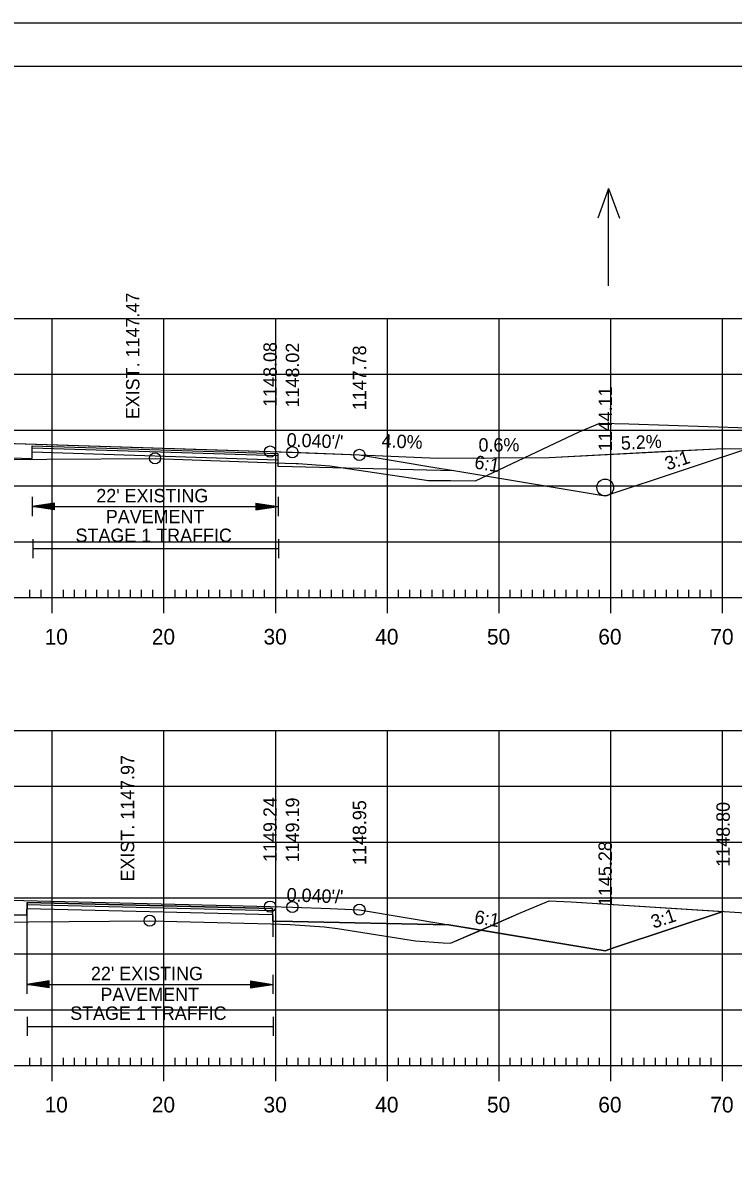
# Model space of a CAD drawing. Extents: x 1322838 to 1324533, y 339903 to 351025.
# Drawn here: x 1323711.1 to 1323774.7, y 342574.4 to 342676.5 of the extents above; entities that cross this region are included whole.
import ezdxf

# ---------------------------------------------------------------- set-up
doc = ezdxf.new("R2010")
doc.units = 0
for name, color, linetype in [('R_Alt Surface', 7, 'Continuous'), ('R_Axis', 7, 'Continuous'), ('R_Axis Annot', 7, 'Continuous'), ('R_Border', 7, 'Continuous'), ('R_Drive', 7, 'Continuous'), ('R_Exist Surface', 7, 'Continuous'), ('R_Fin Surface', 7, 'Continuous'), ('R_Fin Surface Annot', 7, 'Continuous'), ('R_Grid', 7, 'Continuous'), ('R_No Plot', 7, 'Continuous'), ('R_Water', 7, 'Continuous'), ('R_Water Annot', 7, 'Continuous'), ('R_Xsect Elev', 7, 'Continuous')]:
    doc.layers.add(name, color=color, linetype=linetype)

msp = doc.modelspace()

# ---------------------------------------------------------------- linework, layer by layer
at = {"layer": 'R_Alt Surface'}
for points in [[(1323655.31, 342638.41), (1323672.21, 342638.74), (1323711.91, 342637.5), (1323711.92, 342638.63), (1323733.91, 342637.94), (1323733.92, 342636.82), (1323735.22, 342636.78), (1323749.68, 342636.42)], [(1323655.61, 342597.23), (1323672.21, 342597.56), (1323711.45, 342596.62), (1323711.46, 342597.75), (1323733.44, 342597.22), (1323733.45, 342596.1), (1323735.22, 342596.05), (1323749.21, 342595.77)]]:
    msp.add_lwpolyline(points, dxfattribs=at)
at = {"layer": 'R_Axis'}
for p, q in [((1323713.72, 342623.65), (1323713.72, 342626.45)), ((1323723.72, 342623.65), (1323723.72, 342626.45)), ((1323733.72, 342623.65), (1323733.72, 342626.45)), ((1323743.72, 342623.65), (1323743.72, 342626.45)), ((1323753.72, 342623.65), (1323753.72, 342626.45)), ((1323763.72, 342623.65), (1323763.72, 342626.45)), ((1323773.72, 342623.65), (1323773.72, 342626.45)), ((1323563.72, 342625.05), (1323843.72, 342625.05)), ((1323711.72, 342625.05), (1323711.72, 342625.75)), ((1323712.72, 342625.05), (1323712.72, 342625.75)), ((1323714.72, 342625.05), (1323714.72, 342625.75)), ((1323715.72, 342625.05), (1323715.72, 342625.75)), ((1323716.72, 342625.05), (1323716.72, 342625.75)), ((1323717.72, 342625.05), (1323717.72, 342625.75)), ((1323718.72, 342625.05), (1323718.72, 342625.75)), ((1323719.72, 342625.05), (1323719.72, 342625.75)), ((1323720.72, 342625.05), (1323720.72, 342625.75)), ((1323721.72, 342625.05), (1323721.72, 342625.75)), ((1323722.72, 342625.05), (1323722.72, 342625.75)), ((1323724.72, 342625.05), (1323724.72, 342625.75)), ((1323725.72, 342625.05), (1323725.72, 342625.75)), ((1323726.72, 342625.05), (1323726.72, 342625.75)), ((1323727.72, 342625.05), (1323727.72, 342625.75)), ((1323728.72, 342625.05), (1323728.72, 342625.75)), ((1323729.72, 342625.05), (1323729.72, 342625.75)), ((1323730.72, 342625.05), (1323730.72, 342625.75)), ((1323731.72, 342625.05), (1323731.72, 342625.75)), ((1323732.72, 342625.05), (1323732.72, 342625.75)), ((1323734.72, 342625.05), (1323734.72, 342625.75)), ((1323735.72, 342625.05), (1323735.72, 342625.75)), ((1323736.72, 342625.05), (1323736.72, 342625.75)), ((1323737.72, 342625.05), (1323737.72, 342625.75)), ((1323738.72, 342625.05), (1323738.72, 342625.75)), ((1323739.72, 342625.05), (1323739.72, 342625.75)), ((1323740.72, 342625.05), (1323740.72, 342625.75)), ((1323741.72, 342625.05), (1323741.72, 342625.75)), ((1323742.72, 342625.05), (1323742.72, 342625.75)), ((1323744.72, 342625.05), (1323744.72, 342625.75)), ((1323745.72, 342625.05), (1323745.72, 342625.75)), ((1323746.72, 342625.05), (1323746.72, 342625.75)), ((1323747.72, 342625.05), (1323747.72, 342625.75)), ((1323748.72, 342625.05), (1323748.72, 342625.75)), ((1323749.72, 342625.05), (1323749.72, 342625.75)), ((1323750.72, 342625.05), (1323750.72, 342625.75)), ((1323751.72, 342625.05), (1323751.72, 342625.75)), ((1323752.72, 342625.05), (1323752.72, 342625.75)), ((1323754.72, 342625.05), (1323754.72, 342625.75)), ((1323755.72, 342625.05), (1323755.72, 342625.75)), ((1323756.72, 342625.05), (1323756.72, 342625.75)), ((1323757.72, 342625.05), (1323757.72, 342625.75)), ((1323758.72, 342625.05), (1323758.72, 342625.75)), ((1323759.72, 342625.05), (1323759.72, 342625.75)), ((1323760.72, 342625.05), (1323760.72, 342625.75)), ((1323761.72, 342625.05), (1323761.72, 342625.75)), ((1323762.72, 342625.05), (1323762.72, 342625.75)), ((1323764.72, 342625.05), (1323764.72, 342625.75)), ((1323765.72, 342625.05), (1323765.72, 342625.75)), ((1323766.72, 342625.05), (1323766.72, 342625.75)), ((1323767.72, 342625.05), (1323767.72, 342625.75)), ((1323768.72, 342625.05), (1323768.72, 342625.75)), ((1323769.72, 342625.05), (1323769.72, 342625.75)), ((1323770.72, 342625.05), (1323770.72, 342625.75)), ((1323771.72, 342625.05), (1323771.72, 342625.75)), ((1323772.72, 342625.05), (1323772.72, 342625.75)), ((1323713.72, 342581.76), (1323713.72, 342584.56)), ((1323723.72, 342581.76), (1323723.72, 342584.56)), ((1323733.72, 342581.76), (1323733.72, 342584.56)), ((1323743.72, 342581.76), (1323743.72, 342584.56)), ((1323753.72, 342581.76), (1323753.72, 342584.56)), ((1323763.72, 342581.76), (1323763.72, 342584.56)), ((1323773.72, 342581.76), (1323773.72, 342584.56)), ((1323563.72, 342583.16), (1323843.72, 342583.16)), ((1323711.72, 342583.16), (1323711.72, 342583.86)), ((1323712.72, 342583.16), (1323712.72, 342583.86)), ((1323714.72, 342583.16), (1323714.72, 342583.86)), ((1323715.72, 342583.16), (1323715.72, 342583.86)), ((1323716.72, 342583.16), (1323716.72, 342583.86)), ((1323717.72, 342583.16), (1323717.72, 342583.86)), ((1323718.72, 342583.16), (1323718.72, 342583.86)), ((1323719.72, 342583.16), (1323719.72, 342583.86)), ((1323720.72, 342583.16), (1323720.72, 342583.86)), ((1323721.72, 342583.16), (1323721.72, 342583.86)), ((1323722.72, 342583.16), (1323722.72, 342583.86)), ((1323724.72, 342583.16), (1323724.72, 342583.86)), ((1323725.72, 342583.16), (1323725.72, 342583.86)), ((1323726.72, 342583.16), (1323726.72, 342583.86)), ((1323727.72, 342583.16), (1323727.72, 342583.86)), ((1323728.72, 342583.16), (1323728.72, 342583.86)), ((1323729.72, 342583.16), (1323729.72, 342583.86)), ((1323730.72, 342583.16), (1323730.72, 342583.86)), ((1323731.72, 342583.16), (1323731.72, 342583.86)), ((1323732.72, 342583.16), (1323732.72, 342583.86)), ((1323734.72, 342583.16), (1323734.72, 342583.86)), ((1323735.72, 342583.16), (1323735.72, 342583.86)), ((1323736.72, 342583.16), (1323736.72, 342583.86)), ((1323737.72, 342583.16), (1323737.72, 342583.86)), ((1323738.72, 342583.16), (1323738.72, 342583.86)), ((1323739.72, 342583.16), (1323739.72, 342583.86)), ((1323740.72, 342583.16), (1323740.72, 342583.86)), ((1323741.72, 342583.16), (1323741.72, 342583.86)), ((1323742.72, 342583.16), (1323742.72, 342583.86)), ((1323744.72, 342583.16), (1323744.72, 342583.86)), ((1323745.72, 342583.16), (1323745.72, 342583.86)), ((1323746.72, 342583.16), (1323746.72, 342583.86)), ((1323747.72, 342583.16), (1323747.72, 342583.86)), ((1323748.72, 342583.16), (1323748.72, 342583.86)), ((1323749.72, 342583.16), (1323749.72, 342583.86)), ((1323750.72, 342583.16), (1323750.72, 342583.86)), ((1323751.72, 342583.16), (1323751.72, 342583.86)), ((1323752.72, 342583.16), (1323752.72, 342583.86)), ((1323754.72, 342583.16), (1323754.72, 342583.86)), ((1323755.72, 342583.16), (1323755.72, 342583.86)), ((1323756.72, 342583.16), (1323756.72, 342583.86)), ((1323757.72, 342583.16), (1323757.72, 342583.86)), ((1323758.72, 342583.16), (1323758.72, 342583.86)), ((1323759.72, 342583.16), (1323759.72, 342583.86)), ((1323760.72, 342583.16), (1323760.72, 342583.86)), ((1323761.72, 342583.16), (1323761.72, 342583.86)), ((1323762.72, 342583.16), (1323762.72, 342583.86)), ((1323764.72, 342583.16), (1323764.72, 342583.86)), ((1323765.72, 342583.16), (1323765.72, 342583.86)), ((1323766.72, 342583.16), (1323766.72, 342583.86)), ((1323767.72, 342583.16), (1323767.72, 342583.86)), ((1323768.72, 342583.16), (1323768.72, 342583.86)), ((1323769.72, 342583.16), (1323769.72, 342583.86)), ((1323770.72, 342583.16), (1323770.72, 342583.86)), ((1323771.72, 342583.16), (1323771.72, 342583.86)), ((1323772.72, 342583.16), (1323772.72, 342583.86))]:
    msp.add_line(p, q, dxfattribs=at)
at = {"layer": 'R_Axis Annot'}
for p, q in [((1323711.93, 342634.06), (1323711.93, 342632.35)), ((1323733.93, 342634.06), (1323733.93, 342632.35)), ((1323713.93, 342633.51), (1323711.93, 342633.21)), ((1323713.93, 342632.91), (1323711.93, 342633.21)), ((1323711.93, 342633.21), (1323733.93, 342633.21)), ((1323713.93, 342633.46), (1323712.27, 342633.21)), ((1323713.93, 342632.96), (1323712.27, 342633.21)), ((1323713.93, 342633.4), (1323712.61, 342633.21)), ((1323713.93, 342633.01), (1323712.61, 342633.21)), ((1323713.93, 342633.35), (1323712.94, 342633.21)), ((1323713.93, 342633.06), (1323712.94, 342633.21)), ((1323713.93, 342633.3), (1323713.28, 342633.21)), ((1323713.93, 342633.11), (1323713.28, 342633.21)), ((1323713.93, 342633.25), (1323713.62, 342633.21)), ((1323713.93, 342633.16), (1323713.62, 342633.21)), ((1323713.93, 342632.91), (1323713.93, 342633.51)), ((1323731.93, 342633.51), (1323733.93, 342633.21)), ((1323731.93, 342633.51), (1323731.93, 342632.91)), ((1323731.93, 342633.46), (1323733.6, 342633.21)), ((1323731.93, 342633.4), (1323733.25, 342633.21)), ((1323731.93, 342633.35), (1323732.92, 342633.21)), ((1323731.93, 342633.3), (1323732.58, 342633.21)), ((1323731.93, 342633.25), (1323732.25, 342633.21)), ((1323731.93, 342632.91), (1323733.93, 342633.21)), ((1323731.93, 342633.11), (1323732.58, 342633.21)), ((1323731.93, 342633.01), (1323733.25, 342633.21)), ((1323731.93, 342632.96), (1323733.6, 342633.21)), ((1323731.93, 342633.06), (1323732.92, 342633.21)), ((1323731.93, 342633.16), (1323732.25, 342633.21)), ((1323711.97, 342630.29), (1323711.97, 342628.59)), ((1323733.97, 342630.29), (1323733.97, 342628.59)), ((1323711.97, 342629.44), (1323733.97, 342629.44)), ((1323711.45, 342591.28), (1323711.45, 342589.57)), ((1323733.45, 342591.28), (1323733.45, 342589.57)), ((1323713.45, 342590.73), (1323711.45, 342590.43)), ((1323713.45, 342590.13), (1323711.45, 342590.43)), ((1323711.45, 342590.43), (1323733.45, 342590.43)), ((1323713.45, 342590.68), (1323711.78, 342590.43)), ((1323713.45, 342590.18), (1323711.78, 342590.43)), ((1323713.45, 342590.62), (1323712.13, 342590.43)), ((1323713.45, 342590.23), (1323712.13, 342590.43)), ((1323713.45, 342590.57), (1323712.46, 342590.43)), ((1323713.45, 342590.28), (1323712.46, 342590.43)), ((1323713.45, 342590.52), (1323712.8, 342590.43)), ((1323713.45, 342590.33), (1323712.8, 342590.43)), ((1323713.45, 342590.47), (1323713.13, 342590.43)), ((1323713.45, 342590.38), (1323713.13, 342590.43)), ((1323713.45, 342590.13), (1323713.45, 342590.73)), ((1323731.45, 342590.73), (1323733.45, 342590.43)), ((1323731.45, 342590.73), (1323731.45, 342590.13)), ((1323731.45, 342590.68), (1323733.12, 342590.43)), ((1323731.45, 342590.62), (1323732.77, 342590.43)), ((1323731.45, 342590.57), (1323732.44, 342590.43)), ((1323731.45, 342590.52), (1323732.1, 342590.43)), ((1323731.45, 342590.47), (1323731.77, 342590.43)), ((1323731.45, 342590.13), (1323733.45, 342590.43)), ((1323731.45, 342590.33), (1323732.1, 342590.43)), ((1323731.45, 342590.23), (1323732.77, 342590.43)), ((1323731.45, 342590.18), (1323733.12, 342590.43)), ((1323731.45, 342590.28), (1323732.44, 342590.43)), ((1323731.45, 342590.38), (1323731.77, 342590.43)), ((1323711.48, 342587.51), (1323711.48, 342585.81)), ((1323733.48, 342587.51), (1323733.48, 342585.81)), ((1323711.48, 342586.66), (1323733.48, 342586.66))]:
    msp.add_line(p, q, dxfattribs=at)
at = {"layer": 'R_Border'}
msp.add_line((1323545.72, 342672.62), (1323861.9, 342672.62), dxfattribs=at)
at = {"layer": 'R_Drive'}
for p, q in [((1323758.21, 342637.61), (1323773.19, 342638.38)), ((1323773.19, 342638.38), (1323783.19, 342638.44)), ((1323741.22, 342637.83), (1323748.21, 342637.55))]:
    msp.add_line(p, q, dxfattribs=at)
for points in [[(1323748.21, 342637.55), (1323758.21, 342637.61), (1323768.2, 342638.13), (1323773.19, 342638.38)], [(1323773.19, 342638.38), (1323783.19, 342638.44)]]:
    msp.add_lwpolyline(points, dxfattribs=at)
at = {"layer": 'R_Exist Surface'}
for points in [[(1323710.31, 342637.41), (1323713.23, 342637.44), (1323722.92, 342637.52), (1323734.56, 342637.1), (1323735.54, 342637.06), (1323735.72, 342637.05), (1323738.58, 342636.84), (1323739.54, 342636.69), (1323747.39, 342635.54), (1323749.36, 342635.53), (1323751.62, 342635.5), (1323760.89, 342639.89), (1323762.74, 342640.68), (1323765.33, 342640.61), (1323779.53, 342640.13)], [(1323710.2, 342596), (1323711.61, 342596.02), (1323722.45, 342596.13), (1323733.3, 342595.85), (1323735.01, 342595.79), (1323737.65, 342595.62), (1323738.05, 342595.59), (1323739.24, 342595.43), (1323746.24, 342594.32), (1323748.72, 342594.16), (1323749.38, 342594.11), (1323755.7, 342596.85), (1323758.2, 342597.92), (1323760.18, 342597.81), (1323780.01, 342596.57)]]:
    msp.add_lwpolyline(points, dxfattribs=at)
at = {"layer": 'R_Fin Surface'}
for points in [[(1323646.43, 342636.93), (1323655.31, 342638.41), (1323657.5, 342638.77), (1323666.21, 342640.22), (1323667.41, 342640.19), (1323672.21, 342640.04), (1323673.81, 342639.99), (1323674.21, 342639.97), (1323697.81, 342639.24), (1323703.72, 342639.05), (1323727.32, 342638.32), (1323733.22, 342638.13), (1323734.82, 342638.08), (1323735.22, 342638.07), (1323736.41, 342638.02), (1323741.22, 342637.83), (1323747.97, 342636.7), (1323749.68, 342636.42), (1323760.52, 342634.61), (1323763.22, 342634.16), (1323777.23, 342638.83), (1323780.77, 342640.01)], [(1323666.21, 342640.22), (1323672.21, 342640.04), (1323674.21, 342639.97), (1323703.72, 342639.05), (1323733.22, 342638.13), (1323735.22, 342638.07), (1323741.22, 342637.83)], [(1323651.03, 342596.46), (1323655.61, 342597.23), (1323655.61, 342597.23), (1323661.83, 342598.27), (1323666.22, 342599), (1323668.07, 342598.95), (1323672.21, 342598.85), (1323672.22, 342598.85), (1323673.25, 342598.83), (1323674.22, 342598.81), (1323703.72, 342598.1), (1323729.6, 342597.48), (1323733.22, 342597.39), (1323735.22, 342597.35), (1323738.61, 342597.21), (1323741.22, 342597.11), (1323749.21, 342595.77), (1323762.11, 342593.62), (1323763.22, 342593.44), (1323764.15, 342593.75), (1323773.77, 342596.96)]]:
    msp.add_lwpolyline(points, dxfattribs=at)
at = {"layer": 'R_Grid'}
for p, q in [((1323563.72, 342650.05), (1323843.72, 342650.05)), ((1323713.72, 342625.05), (1323713.72, 342650.05)), ((1323723.72, 342625.05), (1323723.72, 342650.05)), ((1323733.72, 342625.05), (1323733.72, 342650.05)), ((1323743.72, 342625.05), (1323743.72, 342650.05)), ((1323753.72, 342625.05), (1323753.72, 342650.05)), ((1323763.72, 342625.05), (1323763.72, 342650.05)), ((1323773.72, 342625.05), (1323773.72, 342650.05)), ((1323563.72, 342645.05), (1323843.72, 342645.05)), ((1323563.72, 342640.05), (1323843.72, 342640.05)), ((1323563.72, 342635.05), (1323843.72, 342635.05)), ((1323563.72, 342630.05), (1323843.72, 342630.05)), ((1323563.72, 342625.05), (1323843.72, 342625.05)), ((1323563.72, 342613.16), (1323843.72, 342613.16)), ((1323713.72, 342583.16), (1323713.72, 342613.16)), ((1323723.72, 342583.16), (1323723.72, 342613.16)), ((1323733.72, 342583.16), (1323733.72, 342613.16)), ((1323743.72, 342583.16), (1323743.72, 342613.16)), ((1323753.72, 342583.16), (1323753.72, 342613.16)), ((1323763.72, 342583.16), (1323763.72, 342613.16)), ((1323773.72, 342583.16), (1323773.72, 342613.16)), ((1323563.72, 342608.16), (1323843.72, 342608.16)), ((1323563.72, 342603.16), (1323843.72, 342603.16)), ((1323563.72, 342598.16), (1323843.72, 342598.16)), ((1323563.72, 342593.16), (1323843.72, 342593.16)), ((1323563.72, 342588.16), (1323843.72, 342588.16)), ((1323563.72, 342583.16), (1323843.72, 342583.16))]:
    msp.add_line(p, q, dxfattribs=at)
at = {"layer": 'R_No Plot'}
for p, q in [((1323533.31, 342676.51), (1323866.65, 342676.51)), ((1323711.91, 342638.09), (1323733.9, 342637.4)), ((1323711.45, 342597.39), (1323711.45, 342591.28)), ((1323711.45, 342597.21), (1323733.44, 342596.68)), ((1323733.45, 342596.1), (1323733.45, 342594.69))]:
    msp.add_line(p, q, dxfattribs=at)
for points in [[(1323533.31, 342676.51), (1323866.65, 342676.51), (1323866.65, 342463.18), (1323533.31, 342463.18)], [(1323779.64, 342672.62), (1323799.26, 342672.62), (1323799.26, 342662.74), (1323815.37, 342662.74), (1323838.57, 342662.74), (1323838.57, 342630.07), (1323861.77, 342630.07), (1323861.9, 342467.16), (1323545.72, 342467.16), (1323545.72, 342672.62)], [(1323752.11, 342595.29), (1323755.7, 342596.85), (1323758.2, 342597.92), (1323760.18, 342597.81), (1323773.77, 342596.96), (1323764.15, 342593.75), (1323763.22, 342593.44), (1323762.11, 342593.62)]]:
    msp.add_lwpolyline(points, close=True, dxfattribs=at)
for points in [[(1323711.92, 342638.46), (1323733.91, 342637.77)], [(1323710.2, 342596), (1323711.61, 342596.02), (1323722.45, 342596.13), (1323733.3, 342595.85), (1323735.01, 342595.79), (1323737.65, 342595.62), (1323738.05, 342595.59), (1323739.24, 342595.43), (1323746.24, 342594.32), (1323748.72, 342594.16), (1323749.38, 342594.11), (1323752.11, 342595.29), (1323749.21, 342595.77), (1323735.22, 342596.05), (1323733.45, 342596.1), (1323733.44, 342597.22), (1323711.46, 342597.75), (1323711.45, 342596.62), (1323689.24, 342597.15)], [(1323711.45, 342597.58), (1323733.44, 342597.05)]]:
    msp.add_lwpolyline(points, dxfattribs=at)
for centre in [(1323733.22, 342638.13), (1323735.22, 342638.07), (1323741.22, 342637.83), (1323722.92, 342637.52), (1323733.22, 342597.39), (1323733.22, 342597.39), (1323735.22, 342597.35), (1323735.22, 342597.35), (1323741.22, 342597.11), (1323741.22, 342597.11), (1323722.45, 342596.13)]:
    msp.add_circle(centre, 0.5, dxfattribs=at)
at = {"layer": 'R_Water'}
msp.add_circle((1323763.22, 342634.91), 0.75, dxfattribs=at)
at = {"layer": 'R_Water Annot'}
for p, q in [((1323763.52, 342661.67), (1323762.56, 342659.01)), ((1323763.52, 342652.98), (1323763.52, 342661.67)), ((1323763.52, 342661.67), (1323764.49, 342659.01))]:
    msp.add_line(p, q, dxfattribs=at)

# ---------------------------------------------------------------- texts
at = {"layer": 'R_Axis Annot'}
for s, height, p in [("22' EXISTING ", 1.2, (1323717.66, 342633.58)), ('PAVEMENT', 1.2, (1323718.51, 342631.71)), ('STAGE 1 TRAFFIC', 1.2, (1323715.8, 342630.03)), ('10', 1.4, (1323713.03, 342620.85)), ('20', 1.4, (1323722.63, 342620.85)), ('30', 1.4, (1323732.63, 342620.85)), ('40', 1.4, (1323742.63, 342620.85)), ('50', 1.4, (1323752.63, 342620.85)), ('60', 1.4, (1323762.6, 342620.85)), ('70', 1.4, (1323772.63, 342620.85)), ("22' EXISTING ", 1.2, (1323717.18, 342590.8)), ('PAVEMENT', 1.2, (1323718.03, 342588.93)), ('STAGE 1 TRAFFIC', 1.2, (1323715.32, 342587.25)), ('10', 1.4, (1323713.03, 342578.96)), ('20', 1.4, (1323722.63, 342578.96)), ('30', 1.4, (1323732.63, 342578.96)), ('40', 1.4, (1323742.63, 342578.96)), ('50', 1.4, (1323752.63, 342578.96)), ('60', 1.4, (1323762.6, 342578.96)), ('70', 1.4, (1323772.63, 342578.96))]:
    msp.add_text(s, height=height, dxfattribs=at).set_placement(p)
at = {"layer": 'R_Drive'}
for s, rotation, p in [('4.0% ', 357.7093, (1323743.19, 342638.51)), ('0.6% ', 0.3393, (1323751.88, 342638.12)), ('5.2% ', 2.9693, (1323764.65, 342638.28))]:
    msp.add_text(s, height=1.2, rotation=rotation, dxfattribs=at).set_placement(p)
at = {"layer": 'R_Fin Surface Annot'}
for s, rotation, p in [('1148.08', 90, (1323733.82, 342642.13)), ('1148.02', 90, (1323735.82, 342642.07)), ('1147.78', 90, (1323741.82, 342641.83)), ('1144.11', 90, (1323763.82, 342638.16)), ("0.040'/'", 357.7093, (1323734.68, 342638.59)), ('3:1', 18.4339, (1323768.8, 342636.43)), ('6:1', 350.5369, (1323751.45, 342636.63)), ('1149.24', 90, (1323733.82, 342601.39)), ('1149.19', 90, (1323735.82, 342601.35)), ('1148.95', 90, (1323741.82, 342601.11)), ('1148.80', 90, (1323774.37, 342600.96)), ('1145.28', 90, (1323763.82, 342597.44)), ("0.040'/'", 357.7093, (1323734.68, 342597.87)), ('6:1', 350.5394, (1323751.45, 342595.91)), ('3:1', 18.4316, (1323767.55, 342595.41))]:
    msp.add_text(s, height=1.2, rotation=rotation, dxfattribs=at).set_placement(p)
at = {"layer": 'R_Xsect Elev'}
for s, p in [('EXIST. 1147.47', (1323721.52, 342641.02)), ('EXIST. 1147.97', (1323721.05, 342599.63))]:
    msp.add_text(s, height=1.2, rotation=90, dxfattribs=at).set_placement(p)

doc.saveas('drawing.dxf')
